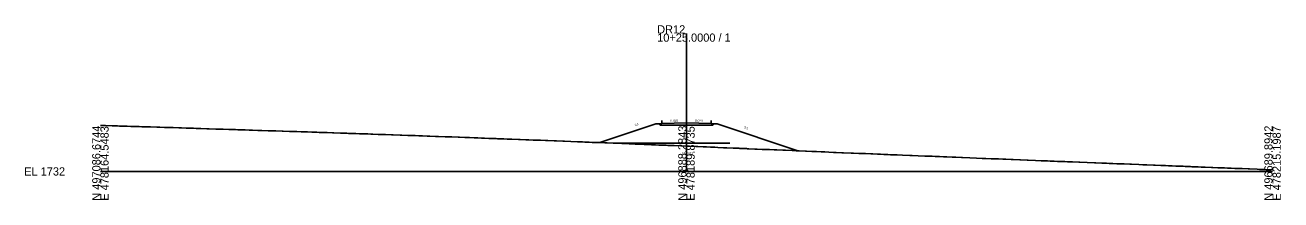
# Model space of a CAD drawing. Extents: x -26 to 403, y -10 to 3574.
# Drawn here: x -25.7 to 402.8, y 490.3 to 549.8 of the extents above; entities that cross this region are included whole.
import ezdxf

# ---------------------------------------------------------------- set-up
doc = ezdxf.new("R2010")
doc.units = 0
for name, color, linetype in [('Exist Cross Section Cell', 7, 'Continuous'), ('Exist XS Center Line Elevation Label', 7, 'Continuous'), ('Exist XS Ground Line', 7, 'Continuous'), ('Prop XS Earthwork Shape', 7, 'Continuous'), ('Prop XS EOT Tick Mark', 7, 'Continuous'), ('Prop XS Finish Grade', 7, 'Continuous'), ('Prop XS Finish Grade Earthwork', 7, 'Continuous'), ('Prop XS Finish Grade Pavement', 7, 'Continuous'), ('Prop XS Pvmt Edge Slope', 7, 'Continuous'), ('Prop XS SE Text', 7, 'Continuous'), ('Prop XS Shoulder Borrow Shape', 7, 'Continuous'), ('Prop XS Side Slope Text', 7, 'Continuous'), ('Prop XS Subgrade Earthwork', 7, 'Continuous'), ('Scratch_Level_4', 7, 'Continuous'), ('Scratch_Level_8', 7, 'Continuous')]:
    doc.layers.add(name, color=color, linetype=linetype)

msp = doc.modelspace()

# ---------------------------------------------------------------- linework, layer by layer
at = {"layer": 'Exist Cross Section Cell'}
for p, q in [((200, 500), (200, 547)), ((0, 500), (200, 500)), ((200, 500), (400, 500))]:
    msp.add_line(p, q, dxfattribs=at)
at = {"layer": 'Exist XS Ground Line'}
msp.add_lwpolyline([(0, 515.67), (0.44, 515.65), (1.69, 515.62), (4.05, 515.55), (5.89, 515.49), (6.57, 515.47), (8.12, 515.43), (9.09, 515.4), (10.34, 515.36), (11.61, 515.32), (13.25, 515.27), (14.13, 515.24), (16.18, 515.18), (16.66, 515.17), (17.05, 515.16), (19.31, 515.08), (20.26, 515.05), (21.89, 515), (24.21, 514.93), (24.79, 514.91), (26.74, 514.85), (27.71, 514.82), (29.25, 514.77), (30.45, 514.74), (31.78, 514.69), (32.7, 514.66), (34.3, 514.61), (36.35, 514.55), (37.08, 514.52), (39.39, 514.45), (39.84, 514.44), (41.85, 514.37), (43.86, 514.3), (44.37, 514.29), (46.12, 514.23), (46.89, 514.21), (48.35, 514.16), (49.42, 514.13), (50.79, 514.08), (51.94, 514.05), (53.7, 513.98), (54.46, 513.96), (55.04, 513.94), (57.26, 513.87), (59.52, 513.79), (59.83, 513.78), (62.02, 513.71), (62.35, 513.7), (64.54, 513.63), (65.27, 513.61), (67.06, 513.55), (68.47, 513.51), (69.59, 513.47), (70.7, 513.44), (72.1, 513.39), (73.89, 513.33), (74.62, 513.3), (76.81, 513.23), (77.38, 513.21), (79.21, 513.14), (79.66, 513.13), (81.88, 513.05), (82.19, 513.04), (84.11, 512.98), (84.7, 512.96), (85.45, 512.94), (87.22, 512.88), (88.36, 512.84), (89.74, 512.8), (91.27, 512.75), (92.25, 512.72), (93.02, 512.69), (94.78, 512.63), (95.29, 512.61), (97.3, 512.54), (99.33, 512.47), (99.89, 512.45), (102.34, 512.37), (102.82, 512.35), (104.86, 512.28), (106.45, 512.22), (107.37, 512.19), (108.68, 512.14), (109.9, 512.1), (111.46, 512.04), (112.43, 512.01), (114.36, 511.94), (114.94, 511.92), (115.39, 511.9), (117.61, 511.82), (118.81, 511.77), (119.98, 511.73), (122.12, 511.65), (122.51, 511.63), (124.34, 511.56), (125.02, 511.54), (125.9, 511.5), (127.54, 511.44), (128.82, 511.39), (130.06, 511.35), (131.03, 511.31), (132.59, 511.25), (133.26, 511.23), (135.11, 511.16), (135.52, 511.14), (137.62, 511.06), (138.85, 511.02), (140.35, 510.96), (142.66, 510.87), (143.26, 510.84), (145.19, 510.77), (146.18, 510.74), (147.7, 510.68), (148.91, 510.63), (150.22, 510.59), (151.87, 510.53), (152.74, 510.5), (154.8, 510.42), (155.27, 510.4), (155.63, 510.39), (157.86, 510.3), (158.37, 510.28), (160.59, 510.19), (162.83, 510.1), (164.56, 510.03), (165.35, 510), (166.82, 509.94), (167.87, 509.9), (169.22, 509.85), (170.39, 509.8), (172.13, 509.73), (172.9, 509.7), (175.03, 509.62), (175.42, 509.61), (177.98, 509.5), (180.48, 509.4), (182.45, 509.32), (182.99, 509.3), (184.69, 509.23), (185.51, 509.2), (186.56, 509.15), (188.03, 509.09), (189.48, 509.03), (190.54, 508.99), (192.37, 508.92), (193.06, 508.89), (193.6, 508.87), (195.85, 508.78), (198.1, 508.69), (200, 508.61), (200.64, 508.58), (201, 508.57), (203.15, 508.48), (203.89, 508.45), (205.67, 508.37), (206.8, 508.33), (208.19, 508.27), (209.7, 508.21), (210.72, 508.16), (212.62, 508.09), (213.24, 508.06), (213.72, 508.04), (215.98, 507.94), (217.86, 507.87), (218.26, 507.85), (220.46, 507.76), (220.8, 507.74), (221.23, 507.72), (223.31, 507.63), (224.12, 507.6), (225.83, 507.52), (227.03, 507.47), (228.34, 507.42), (229.93, 507.35), (230.88, 507.31), (232.84, 507.23), (233.39, 507.21), (233.82, 507.19), (236.08, 507.1), (237.39, 507.04), (238.43, 507), (240.56, 506.9), (240.95, 506.89), (242.81, 506.81), (243.47, 506.78), (244.33, 506.74), (246, 506.67), (247.23, 506.62), (248.52, 506.56), (250.13, 506.5), (251.04, 506.46), (253.03, 506.38), (253.55, 506.36), (256.19, 506.25), (257, 506.22), (258.84, 506.14), (261.12, 506.05), (262.9, 505.97), (263.64, 505.94), (265.14, 505.88), (266.16, 505.84), (267.38, 505.79), (268.67, 505.74), (269.62, 505.7), (271.2, 505.64), (271.87, 505.61), (273.72, 505.54), (276.24, 505.44), (277.03, 505.41), (279.03, 505.33), (281.28, 505.24), (281.92, 505.22), (283.8, 505.14), (284.82, 505.1), (286.32, 505.04), (287.73, 504.98), (288.84, 504.93), (290.62, 504.86), (291.36, 504.83), (291.94, 504.81), (293.88, 504.73), (294.19, 504.72), (296.65, 504.62), (298.92, 504.53), (300.92, 504.45), (301.44, 504.42), (302.11, 504.4), (303.96, 504.33), (305.01, 504.29), (306.48, 504.23), (307.91, 504.17), (309, 504.13), (310.81, 504.06), (311.52, 504.03), (313.71, 503.94), (314.04, 503.93), (316.23, 503.84), (316.61, 503.82), (319.09, 503.72), (320.99, 503.65), (321.6, 503.62), (323.24, 503.56), (324.13, 503.52), (325.48, 503.47), (326.64, 503.42), (327.72, 503.38), (329.16, 503.33), (329.97, 503.29), (331.68, 503.22), (333.88, 503.14), (334.2, 503.12), (336.77, 503.03), (339.24, 502.93), (339.68, 502.92), (341.76, 502.84), (343.37, 502.77), (344.29, 502.74), (345.47, 502.69), (346.81, 502.63), (348.37, 502.58), (349.32, 502.54), (351.26, 502.46), (351.84, 502.44), (354.36, 502.35), (355.71, 502.29), (357.06, 502.24), (359.41, 502.15), (359.96, 502.13), (361.92, 502.05), (363.46, 501.98), (364.45, 501.94), (365.7, 501.89), (366.97, 501.84), (367.94, 501.8), (369.49, 501.74), (370.18, 501.71), (372.01, 501.63), (372.42, 501.61), (374.66, 501.53), (375.69, 501.49), (377.04, 501.44), (379.14, 501.36), (379.57, 501.34), (381.37, 501.27), (382.08, 501.24), (383.61, 501.18), (384.61, 501.14), (385.89, 501.09), (387.13, 501.04), (388.78, 500.97), (389.65, 500.94), (391.67, 500.86), (392.17, 500.84), (394.79, 500.73), (395.59, 500.7), (397.45, 500.63), (400, 500.53)], dxfattribs=at)
at = {"layer": 'Prop XS Earthwork Shape'}
msp.add_lwpolyline([(191.54, 515.8), (190.99, 515.79), (190.52, 516.26), (189.54, 516.18), (170.39, 509.8), (172.13, 509.73), (172.9, 509.7), (175.03, 509.62), (175.42, 509.61), (177.98, 509.5), (180.48, 509.4), (182.45, 509.32), (182.99, 509.3), (184.69, 509.23), (185.51, 509.2), (186.56, 509.15), (188.03, 509.09), (189.48, 509.03), (190.54, 508.99), (192.37, 508.92), (193.06, 508.89), (193.6, 508.87), (195.85, 508.78), (198.1, 508.69), (200, 508.61), (200.64, 508.58), (201, 508.57), (203.15, 508.48), (203.89, 508.45), (205.67, 508.37), (206.8, 508.33), (208.19, 508.27), (209.7, 508.21), (210.72, 508.16), (212.62, 508.09), (213.24, 508.06), (213.72, 508.04), (215.98, 507.94), (217.86, 507.87), (218.26, 507.85), (220.46, 507.76), (220.8, 507.74), (221.23, 507.72), (223.31, 507.63), (224.12, 507.6), (225.83, 507.52), (227.03, 507.47), (228.34, 507.42), (229.93, 507.35), (230.88, 507.31), (232.84, 507.23), (233.39, 507.21), (233.82, 507.19), (236.08, 507.1), (237.39, 507.04), (237.95, 507.02), (210.46, 516.18), (209.48, 516.26), (209.01, 515.79), (208.46, 515.8)], close=True, dxfattribs=at)
at = {"layer": 'Prop XS EOT Tick Mark'}
for p, q in [((191.54, 516.34), (191.54, 517.34)), ((208.46, 516.34), (208.46, 517.34))]:
    msp.add_line(p, q, dxfattribs=at)
at = {"layer": 'Prop XS Finish Grade'}
for p, q in [((191.54, 516.34), (190.52, 516.26)), ((208.46, 516.34), (209.48, 516.26))]:
    msp.add_line(p, q, dxfattribs=at)
at = {"layer": 'Prop XS Finish Grade Earthwork'}
for p, q in [((189.54, 516.18), (170.39, 509.8)), ((190.52, 516.26), (189.54, 516.18)), ((209.48, 516.26), (210.46, 516.18)), ((210.46, 516.18), (237.95, 507.02))]:
    msp.add_line(p, q, dxfattribs=at)
at = {"layer": 'Prop XS Finish Grade Pavement'}
for p, q in [((191.54, 516.34), (200, 516.51)), ((200, 516.51), (208.46, 516.34))]:
    msp.add_line(p, q, dxfattribs=at)
at = {"layer": 'Prop XS Pvmt Edge Slope'}
for p, q in [((191.54, 516.34), (190.99, 515.79)), ((208.46, 516.34), (209.01, 515.79))]:
    msp.add_line(p, q, dxfattribs=at)
at = {"layer": 'Prop XS Shoulder Borrow Shape'}
for points in [[(191.54, 516.34), (190.99, 515.79), (190.52, 516.26)], [(209.01, 515.79), (209.48, 516.26), (208.46, 516.34)]]:
    msp.add_lwpolyline(points, close=True, dxfattribs=at)
at = {"layer": 'Prop XS Subgrade Earthwork'}
for p, q in [((190.99, 515.79), (190.52, 516.26)), ((191.54, 515.8), (190.99, 515.79)), ((191.54, 515.8), (208.46, 515.8)), ((208.46, 515.8), (209.01, 515.79)), ((209.01, 515.79), (209.48, 516.26))]:
    msp.add_line(p, q, dxfattribs=at)
at = {"layer": 'Scratch_Level_4'}
msp.add_line((210.46, 516.18), (237.95, 507.02), dxfattribs=at)
at = {"layer": 'Scratch_Level_8'}
msp.add_line((175.59, 509.6), (214.83, 509.6), dxfattribs=at)

# ---------------------------------------------------------------- texts
at = {"layer": 'Exist Cross Section Cell'}
for s, p in [('DR12', (190, 547)), ('10+25.0000 / 1', (190, 544.2)), ('EL 1732', (-26, 498.6))]:
    msp.add_text(s, height=2.8, dxfattribs=at).set_placement(p)
for s, p in [('N 497086.6744', (0, 490)), ('E 478164.5483', (2.8, 490)), ('N 496888.2843', (200, 490)), ('E 478189.8735', (202.8, 490)), ('N 496689.8942', (400, 490)), ('E 478215.1987', (402.8, 490))]:
    msp.add_text(s, height=2.8, rotation=90, dxfattribs=at).set_placement(p)
at = {"layer": 'Exist XS Center Line Elevation Label'}
msp.add_text('1740.61', height=0.75, dxfattribs=at).set_placement((198.45, 505.86))
at = {"layer": 'Prop XS SE Text'}
for rotation, p in [(1.1458, (194.48, 516.9)), (358.8542, (202.94, 516.95))]:
    msp.add_text('0.020', height=0.75, rotation=rotation, dxfattribs=at).set_placement(p)
at = {"layer": 'Prop XS Side Slope Text'}
for rotation, p in [(18.4349, (182.4, 515.39)), (341.5651, (219.53, 514.74))]:
    msp.add_text('3:1', height=0.75, rotation=rotation, dxfattribs=at).set_placement(p)

doc.saveas('drawing.dxf')
